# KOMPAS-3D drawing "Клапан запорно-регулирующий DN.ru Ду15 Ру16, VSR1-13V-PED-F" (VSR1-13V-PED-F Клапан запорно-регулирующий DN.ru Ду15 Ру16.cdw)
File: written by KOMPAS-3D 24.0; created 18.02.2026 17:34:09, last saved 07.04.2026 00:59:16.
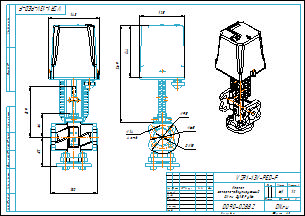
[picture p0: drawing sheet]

Document properties: Автор: R2D2; Форматы листов документа: A3; Полное имя файла: VSR1-13V-PED-F Клапан запорно-регулирующий DN.ru Ду15 Ру16.m3d; Масса: 6.1; Наименование: Клапан запорно-регулирующий DN.ru Ду15 Ру16; Количество листов документа: 1; Примечание: D090-02882

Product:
- Part/product: Клапан запорно-регулирующий DN.ru Ду15 Ру16  | designation VSR1-13V-PED-F
    Масса: 6.1
    Раздел спецификации: Прочие изделия
    Форматы листов документа: A3
    Примечание: D090-02882

Views: Вид 1, Спереди
Referenced files in E:\Работа\Зайцев\Солянка\VSR1-13V-PED-F Клапан запорно-регулирующий DN.ru\DN15\DN15 Kv0.16\: VSR1-13V-PED-F Клапан запорно-регулирующий DN.ru Ду15 Ру16.m3d
Referenced files in E:\Работа\Зайцев\Для компаса\: чертеж DN.ru А3.cdt
Referenced files in E:\Работа\Зайцев\Солянка\VSR1-13V-PED-F Клапан запорно-регулирующий DN.ru\DN15\DN15 Kv0.5\: VSR1-13V-PED-F Клапан запорно-регулирующий DN.ru Ду15 Ру16.m3d
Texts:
  Линейный размер
  VSR1-13V-PED-F
  чертеж DN.ru А3.cdt
  Клапан
  запорно-регулирующий
  DN.ru Ду15 Ру16
  Клапан запорно-регулирующий DN.ru Ду15 Ру16
  VSR1-13V-PED-F Клапан запорно-регулирующий DN.ru Ду15 Ру16
Dimensions and other numbers on the sheet: 0; 3; 2; 4; 130; 82; 143; 64; 139; 1:2; 1; 6,1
